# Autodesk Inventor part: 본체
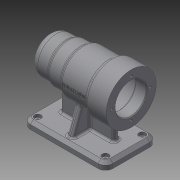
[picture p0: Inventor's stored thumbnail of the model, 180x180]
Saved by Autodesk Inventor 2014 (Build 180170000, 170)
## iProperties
Created: 2016-06
Part Number: 본체
Material: 일반
Document SubType Name: Modeling
Designer: USER
Density: 1 g/cm^3
Appearance: 기본값
Author: USER
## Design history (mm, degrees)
sketch "스케치1"
  geometry: L1 (-56, 0)-(56, 0); L2 (-56, 0)-(-56, 25); L3 (-56, 25)-(-31, 25); L4 (-31, 25)-(-31, 27); L5 (-31, 27)-(-11, 27); L6 (-11, 27)-(-11, 30); L7 (-11, 30)-(28, 30); L8 (28, 30)-(28, 34); L9 (28, 34)-(56, 34); L10 (-50, 0)-(-50, 10.5); L11 (-50, 10.5)-(-47, 10.5); L12 (-47, 10.5)-(-47, 16); L13 (-47, 16)-(-43, 16); L14 (-43, 16)-(-43, 17.5); L15 (-43, 17.5)-(-25, 17.5); L16 (-25, 17.5)-(-25, 21); L17 (-25, 21)-(-13, 21); L18 (-13, 21)-(-13, 24); L19 (-13, 24)-(41, 24); L20 (41, 24)-(41, 21); L21 (41, 21)-(56, 21); L22 (56, 21)-(56, 34); 2 further points
  constraints: 44 end point, 15 parallel, 6 perpendicular, 1 coincident, 1 horizontal, 1 midpoint, 1 point on line
  dimensions: "d0" = 112 distance of L1.start L1.end; "d2" = 25 distance of L2.end L3.end; "d4" = 50 diameter of L3 L1; "d5" = 54 diameter of L5 L1; "d6" = 60 diameter of L7 L1; "d7" = 68 diameter of L9 L1; "d8" = 45 distance between parallel lines of L6 L2; "d9" = 84 distance between parallel lines of L8 L2; "d10" = 3 distance between parallel lines of L12 L10; "d11" = 4 distance between parallel lines of L14 L12; "d12" = 18 distance between parallel lines of L16 L14; "d13" = 12 distance between parallel lines of L18 L16; "d14" = 54 distance between parallel lines of L20 L18; "d15" = 15 distance between parallel lines of L22 L20; "d16" = 112 distance between parallel lines of L2 L22; "d17" = 21 diameter of L11 L1; "d18" = 32 diameter of L13 L1; "d19" = 35 diameter of L15 L1; "d20" = 42 diameter of L17 L1; "d21" = 48 diameter of L19 L1; "d22" = 42 diameter of L21 L1
revolve "회전1" sketch "스케치1" stored, may be unused: angle "d23" = 90 deg
node "작업 평면1"
sketch "스케치2"
  geometry: L1 (-56, -35)-(56, -35); L2 (56, -35)-(56, 35); L3 (56, 35)-(-56, 35); L4 (-56, 35)-(-56, -35); L5 (-56, -35)-(56, 35); L6 (56, -35)-(-56, 35); 1 further point
  constraints: 12 end point, 2 midpoint, 2 parallel, 1 horizontal, 1 perpendicular
  dimensions: "d25" = 112 distance of L3.end L2.end; "d26" = 70 distance of L2.end L1.end
extrude "돌출1" join sketch "스케치2" distance "d27" = 10; taper "d28" = 0 deg
sketch "스케치3"
  geometry: L1 (56, 35)-(-56, 35) reference; L2 (-56, 35)-(-56, -35) reference; L3 (-4, -28)-(4, -28); L4 (4, -28)-(4, 28); L5 (4, 28)-(-4, 28); L6 (-4, 28)-(-4, -28); L7 (-4, -28)-(4, 28); L8 (4, -28)-(-4, 28); L9 (-36, -4)-(36, -4); L10 (36, -4)-(36, 4); L11 (36, 4)-(-36, 4); L12 (-36, 4)-(-36, -4); L13 (-36, -4)-(36, 4); L14 (36, -4)-(-36, 4); 1 further point
  constraints: 24 end point, 4 midpoint, 4 parallel, 2 horizontal, 2 perpendicular
  dimensions: "d29" = 8 distance of L5.end L4.end; "d30" = 7 distance between parallel lines of L1 L5; "d31" = 8 distance of L10.end L9.end; "d32" = 20 distance between parallel lines of L2 L12
extrude "돌출2" join sketch "스케치3" stored distance "d33" = 10; taper "d34" = 0 deg
feature "면 기울기1" dims angle "d35" = 20 deg
feature "면 기울기2" dims angle "d36" = 20 deg
sketch "스케치4"
  geometry: C1 r 34 at (0, 0) reference; 1 further point
  constraints: 1 vertical alignment
  dimensions: "d37" = 26 distance of point (0, 26) C1.centre
hole "구멍1" sketch "스케치4" at (0, 26) diameter "d38" = 3.242; stored, may be unused: countersink angle "d42" = 90 deg, drill point angle "d44" = 118 deg; dims "d39" = 8, "d40" = 4, "d41" = 2, "d43" = 11
sketch "스케치5"
  geometry: L1 (-46, -25)-(46, -25); L2 (46, -25)-(46, 25); L3 (46, 25)-(-46, 25); L4 (-46, 25)-(-46, -25); L5 (-46, -25)-(46, 25); L6 (46, -25)-(-46, 25); 5 further points
  constraints: 12 end point, 4 coincident, 2 midpoint, 2 parallel, 1 horizontal, 1 perpendicular
  dimensions: "d48" = 92 distance of L3.end L2.end; "d49" = 50 distance of L2.end L1.end
hole "구멍2" sketch "스케치5" at (-46, 25), (-46, -25), (46, -25), (46, 25) diameter "d50" = 5; stored, may be unused: countersink angle "d54" = 90 deg, drill point angle "d56" = 118 deg; dims "d51" = 8, "d52" = 9, "d53" = 4, "d55" = 11
fillet "모깎기1" dims "d57" = 3
fillet "모깎기2" dims "d58" = 0.3
chamfer "모따기1" distance "d59" = 1; stored, may be unused: second distance "d60" = 2, angle "d61" = 45 deg
fillet "모깎기3" dims "d62" = 10
chamfer "모따기2" distance "d63" = 4; stored, may be unused: second distance "d64" = 2, angle "d65" = 45 deg
fillet "모깎기4" dims "d66" = 3
fillet "모깎기5" dims "d67" = 3, "d68" = 3
fillet "모깎기6" dims "d69" = 3
fillet "모깎기7" dims "d70" = 3
node "작업 평면4"
sketch "스케치7"
  geometry: L1 (102, 36)-(102, 104) reference; 2 further points
  constraints: 1 horizontal alignment, 1 other
  dimensions: "d74" = 48 distance from line of L1 point (54, 70)
feature "엠보싱1" sketch "스케치7" dims "d0" = 112, "d2" = 25, "d4" = 50, "d5" = 54, "d6" = 60, "d7" = 68, "d8" = 45, "d9" = 84, "d10" = 3, "d11" = 4, "d12" = 18, "d13" = 12, "d14" = 54, "d15" = 15, "d16" = 112, "d17" = 21, "d18" = 32, "d19" = 35, "d20" = 42, "d21" = 48, "d22" = 42, "d75" = 0.5, "d76" = 0
node "솔리드1"
pattern_circular "원형 패턴1" dims angle "d46" = 360 deg
